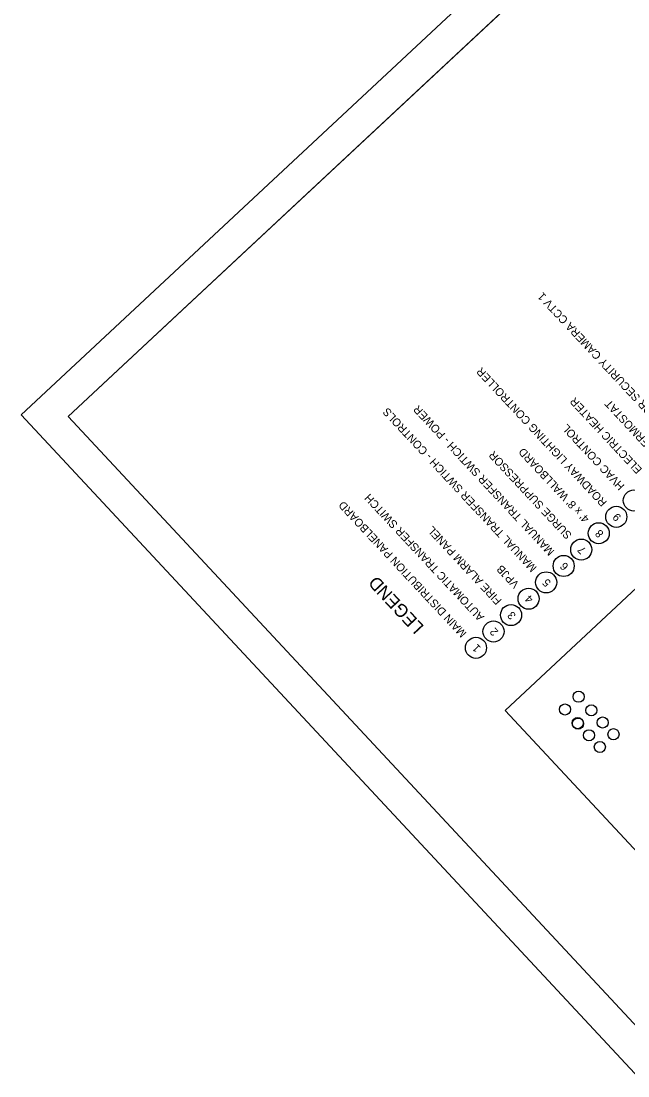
# Model space of a CAD drawing. Extents: x 1121979 to 1130574, y 1838676 to 1848573.
# Drawn here: x 1129608.35 to 1129626.56, y 1839365.55 to 1839397.19 of the extents above; entities that cross this region are included whole.
import ezdxf

# ---------------------------------------------------------------- set-up
doc = ezdxf.new("R2010")
doc.units = 0
for name, color, linetype in [('GE-SHT-Clip Border', 7, 'Continuous'), ('GE-SHT-General', 7, 'Continuous'), ('GE-SHT-Plot Border', 7, 'Continuous'), ('IPDC BUILDING RELATED', 7, 'Continuous'), ('Level 4', 7, 'Continuous'), ('Sheet Text', 7, 'Continuous'), ('Sheets_Printer Plotting Border', 7, 'Continuous')]:
    doc.layers.add(name, color=color, linetype=linetype)

msp = doc.modelspace()

# ---------------------------------------------------------------- linework, layer by layer
at = {"layer": 'GE-SHT-Clip Border'}
msp.add_lwpolyline([(1129652.729, 1839339.252), (1129609.766, 1839385.33), (1129639.021, 1839412.608), (1129681.985, 1839366.531)], close=True, dxfattribs=at)
msp.add_lwpolyline([(1129652.729, 1839339.252), (1129609.766, 1839385.33), (1129639.021, 1839412.608), (1129681.985, 1839366.531)], close=True, dxfattribs=at)
msp.add_lwpolyline([(1129652.729, 1839339.252), (1129609.766, 1839385.33), (1129639.021, 1839412.608), (1129681.985, 1839366.531)], close=True, dxfattribs=at)
at = {"layer": 'GE-SHT-General'}
msp.add_lwpolyline([(1129652.729, 1839339.252), (1129609.766, 1839385.33), (1129640.484, 1839413.972), (1129683.448, 1839367.895)], close=True, dxfattribs=at)
at = {"layer": 'GE-SHT-Plot Border'}
msp.add_lwpolyline([(1129686.907, 1839365.651), (1129640.533, 1839415.386), (1129608.352, 1839385.379), (1129654.726, 1839335.645)], close=True, dxfattribs=at)
at = {"layer": 'IPDC BUILDING RELATED'}
for p in [(1129629.458, 1839382.653), (1129630.258, 1839368.598)]:
    msp.add_line(p, (1129622.876, 1839376.516), dxfattribs=at)
at = {"layer": 'Level 4'}
for centre in [(1129626.742, 1839382.812), (1129626.216, 1839382.321), (1129625.689, 1839381.829), (1129625.163, 1839381.338), (1129624.636, 1839380.847), (1129624.11, 1839380.356), (1129623.583, 1839379.865), (1129623.057, 1839379.374), (1129622.53, 1839378.883), (1129622.004, 1839378.392)]:
    msp.add_circle(centre, 0.316, dxfattribs=at)
at = {"layer": 'Sheets_Printer Plotting Border'}
for centre in [(1129625.084, 1839376.925), (1129625.084, 1839376.925), (1129624.675, 1839376.543), (1129624.675, 1839376.543), (1129625.465, 1839376.517), (1129625.465, 1839376.517), (1129625.056, 1839376.135), (1129625.056, 1839376.135), (1129625.069, 1839376.12), (1129625.069, 1839376.12), (1129625.805, 1839376.152), (1129625.805, 1839376.152), (1129626.131, 1839375.802), (1129626.131, 1839375.802), (1129625.396, 1839375.77), (1129625.396, 1839375.77), (1129625.396, 1839375.77), (1129625.396, 1839375.77), (1129625.722, 1839375.42), (1129625.722, 1839375.42)]:
    msp.add_circle(centre, 0.167, dxfattribs=at)

# ---------------------------------------------------------------- texts
at = {"layer": 'GE-SHT-General'}
msp.add_text('LEGEND', height=0.384, rotation=132.9972, dxfattribs=at).set_placement((1129620.464, 1839379.034))
at = {"layer": 'Level 4'}
for s, p in [('9', (1129626.378, 1839382.323)), ('8', (1129625.852, 1839381.831)), ('7', (1129625.325, 1839381.34)), ('6', (1129624.799, 1839380.849)), ('5', (1129624.272, 1839380.358)), ('4', (1129623.746, 1839379.867)), ('3', (1129623.219, 1839379.376)), ('2', (1129622.692, 1839378.885)), ('1', (1129622.166, 1839378.394))]:
    msp.add_text(s, height=0.24, rotation=132.9971, dxfattribs=at).set_placement(p)
at = {"layer": 'Sheet Text'}
for s, p in [('INTERIOR SECURITY CAMERA CCTV 1', (1129628.058, 1839384.732)), ('ROADWAY LIGHTING CONTROLLER ', (1129625.952, 1839382.768)), ('ELECTRIC HEATER', (1129627.005, 1839383.75)), ('THERMOSTAT', (1129627.532, 1839384.241)), ('MANUAL TRANSFER SWTICH - CONTROLS', (1129623.846, 1839380.803)), ('MANUAL TRANSFER SWTICH - POWER', (1129624.373, 1839381.295)), ('HVAC CONTROL', (1129626.479, 1839383.259)), ('SURGE SUPPRESSOR', (1129624.899, 1839381.786)), ("4' x 8' WALLBOARD", (1129625.426, 1839382.277)), ('AUTOMATIC TRANSFER SWITCH', (1129622.267, 1839379.33)), ('MAIN DISTRIBUTION PANELBOARD', (1129621.74, 1839378.839)), ('FIRE ALARM PANEL', (1129622.793, 1839379.821)), ('VPJB', (1129623.32, 1839380.312))]:
    msp.add_text(s, height=0.24, rotation=133.0067, dxfattribs=at).set_placement(p)

doc.saveas('drawing.dxf')
